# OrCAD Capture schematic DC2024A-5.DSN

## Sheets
1 PAGE5: note: HIGH CURRENT HOT SWAP CONTROLLER WITH I²C COMPATIBLE MONITORING AND EEPROM
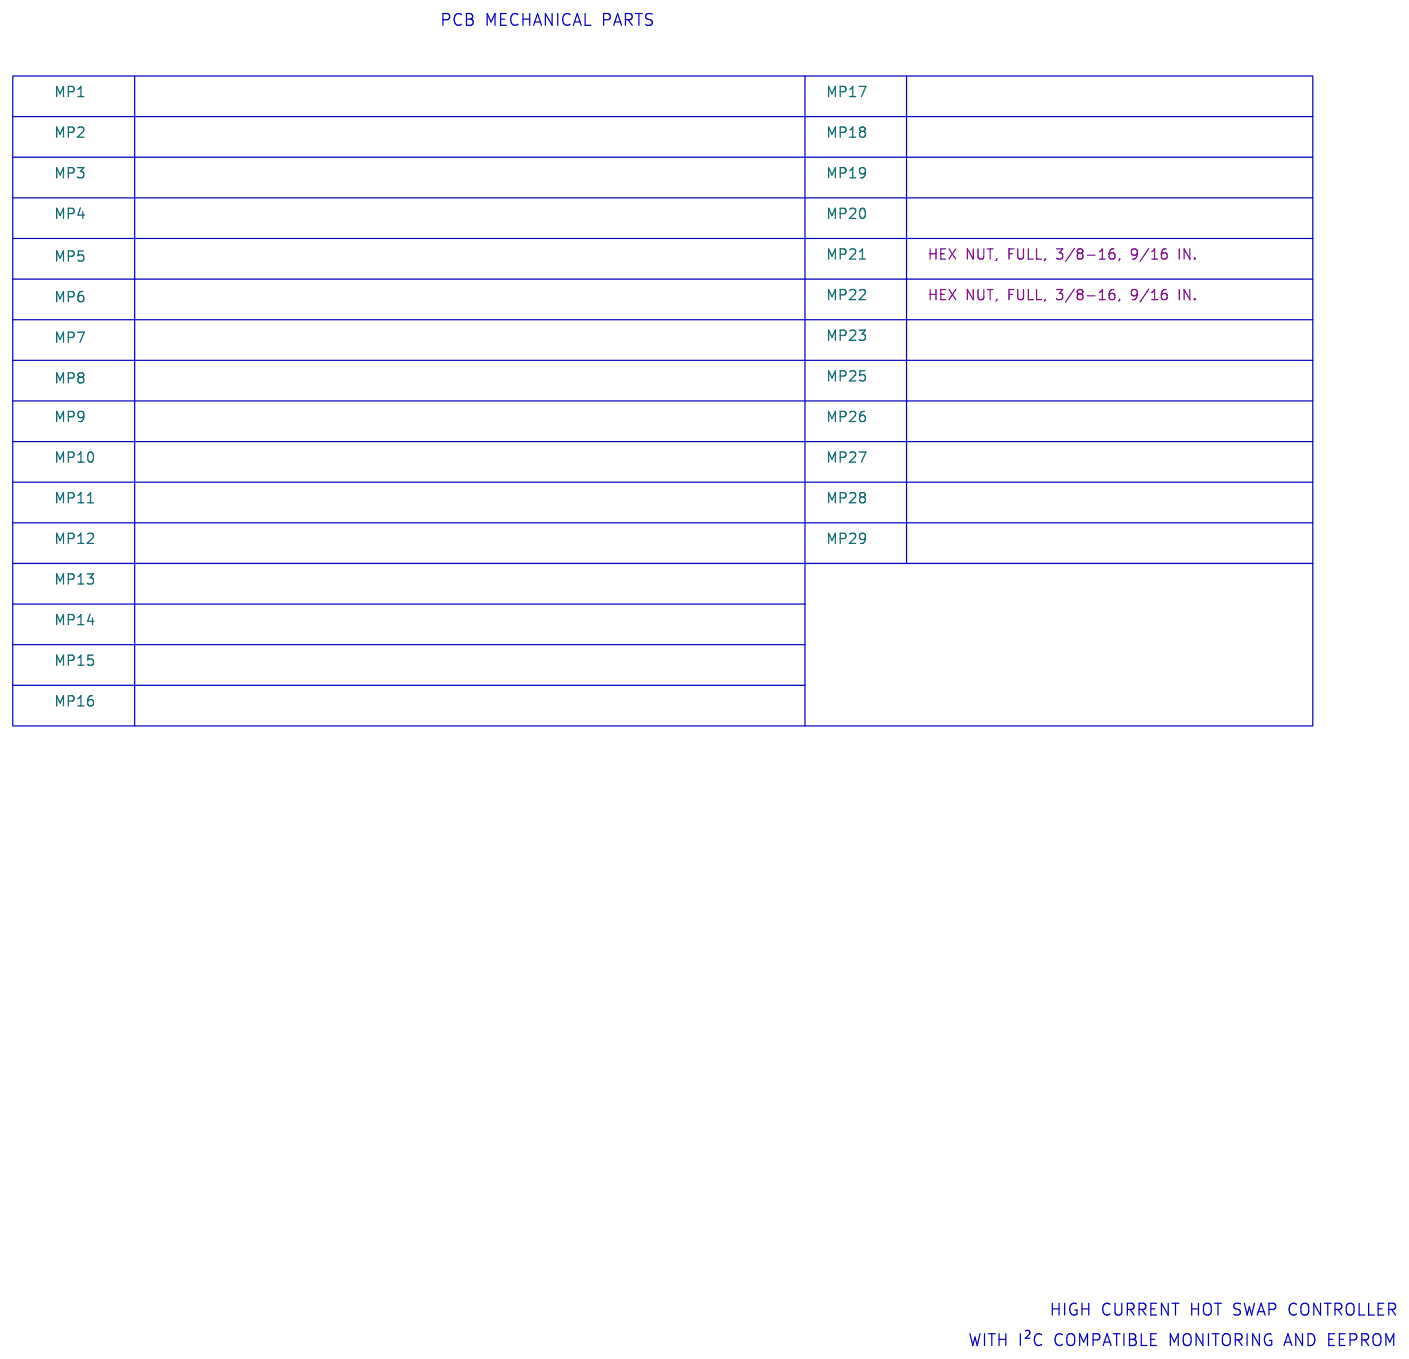
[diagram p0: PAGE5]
2 PAGE1: size Custom
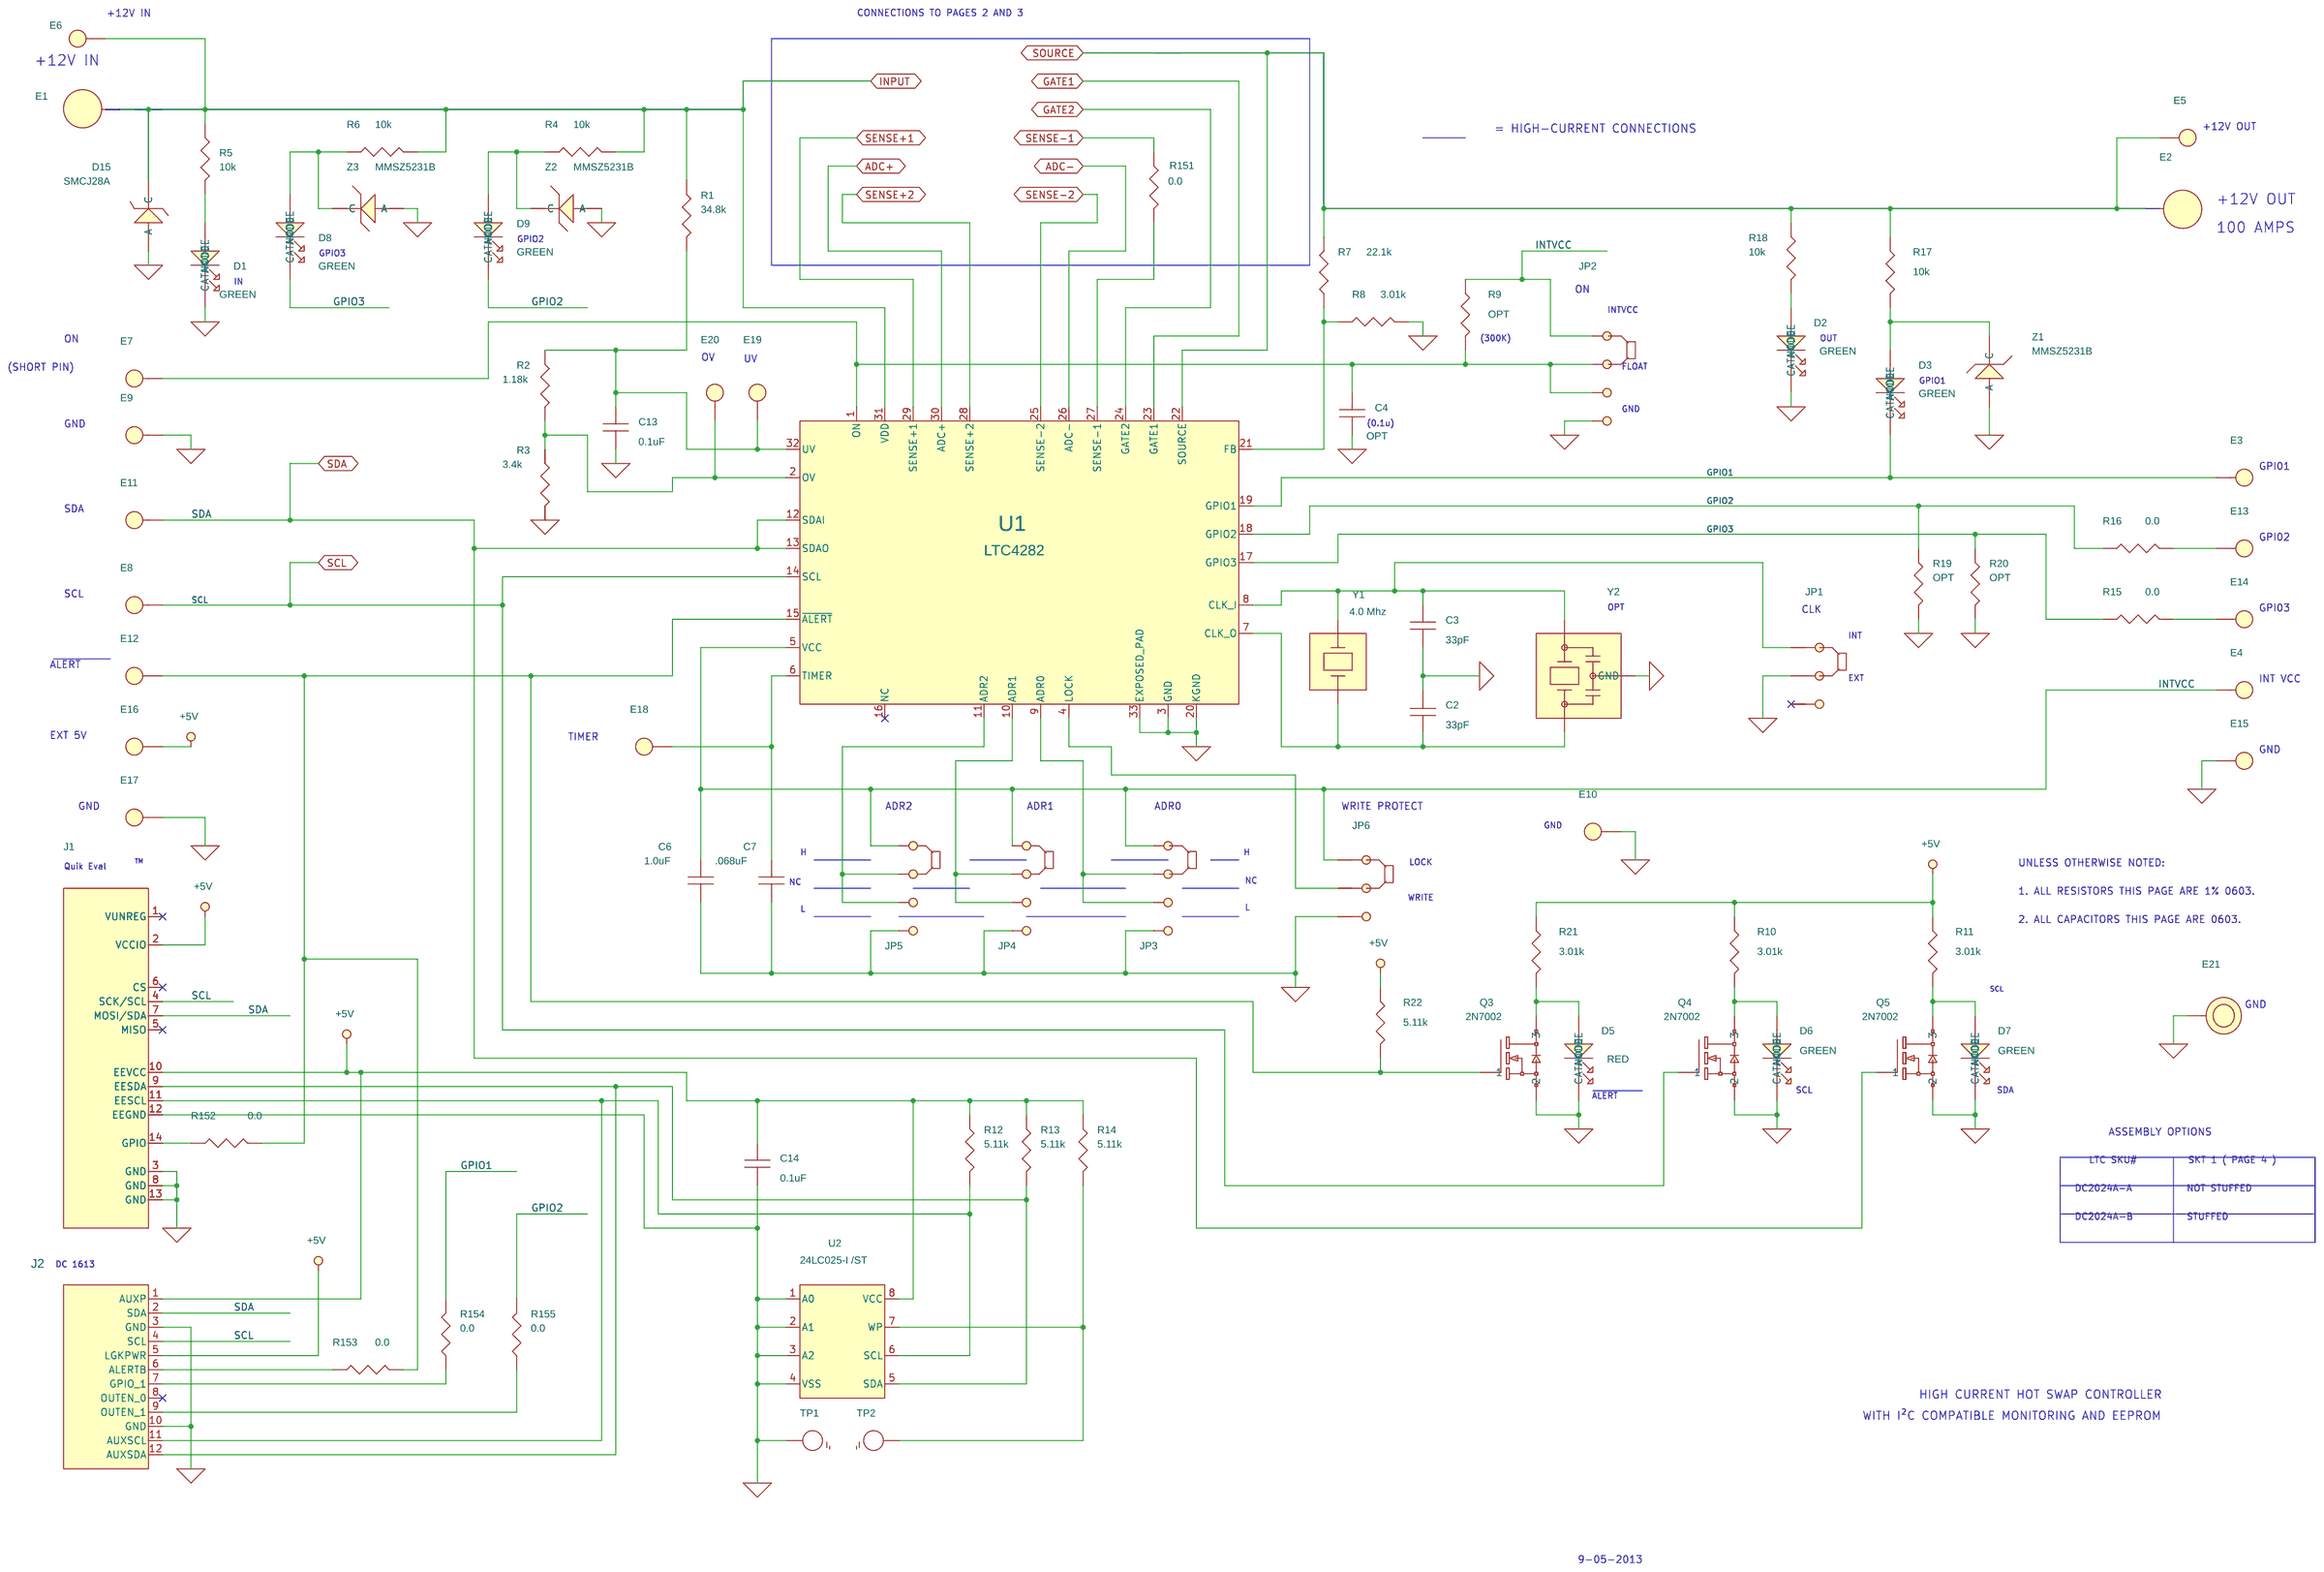
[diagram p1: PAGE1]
3 PAGE2: size Custom
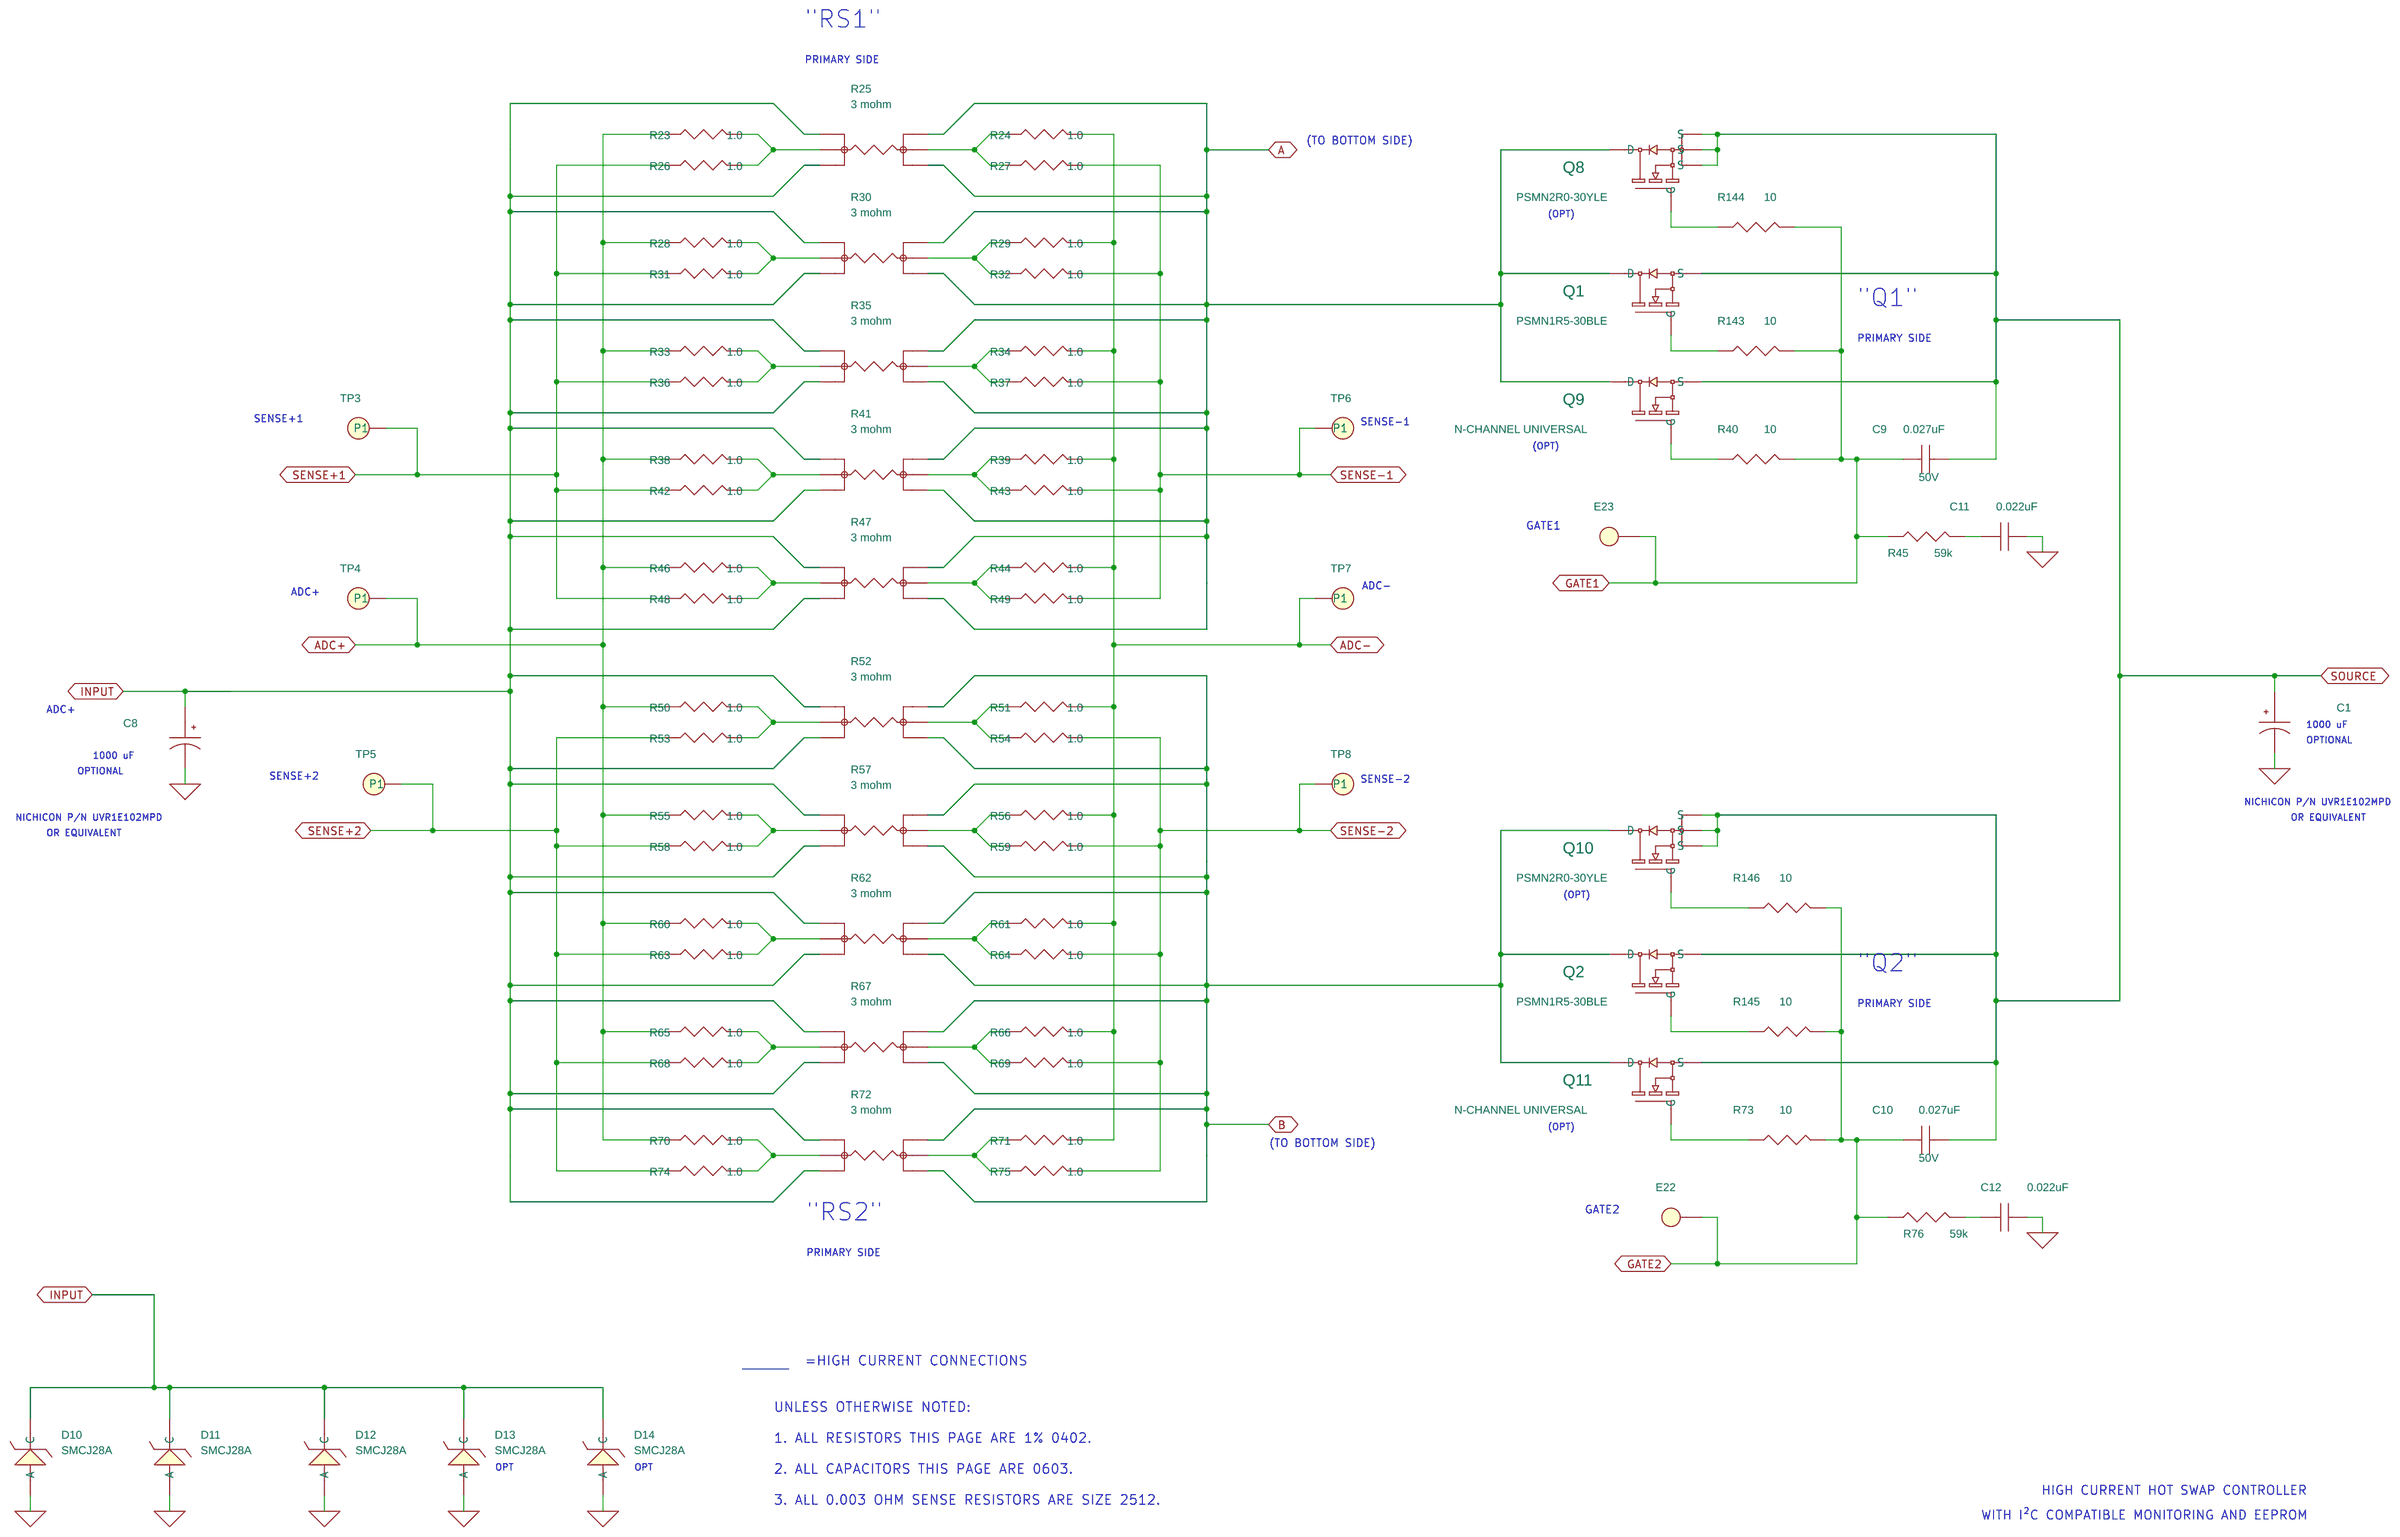
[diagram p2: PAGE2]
4 PAGE3: size Custom
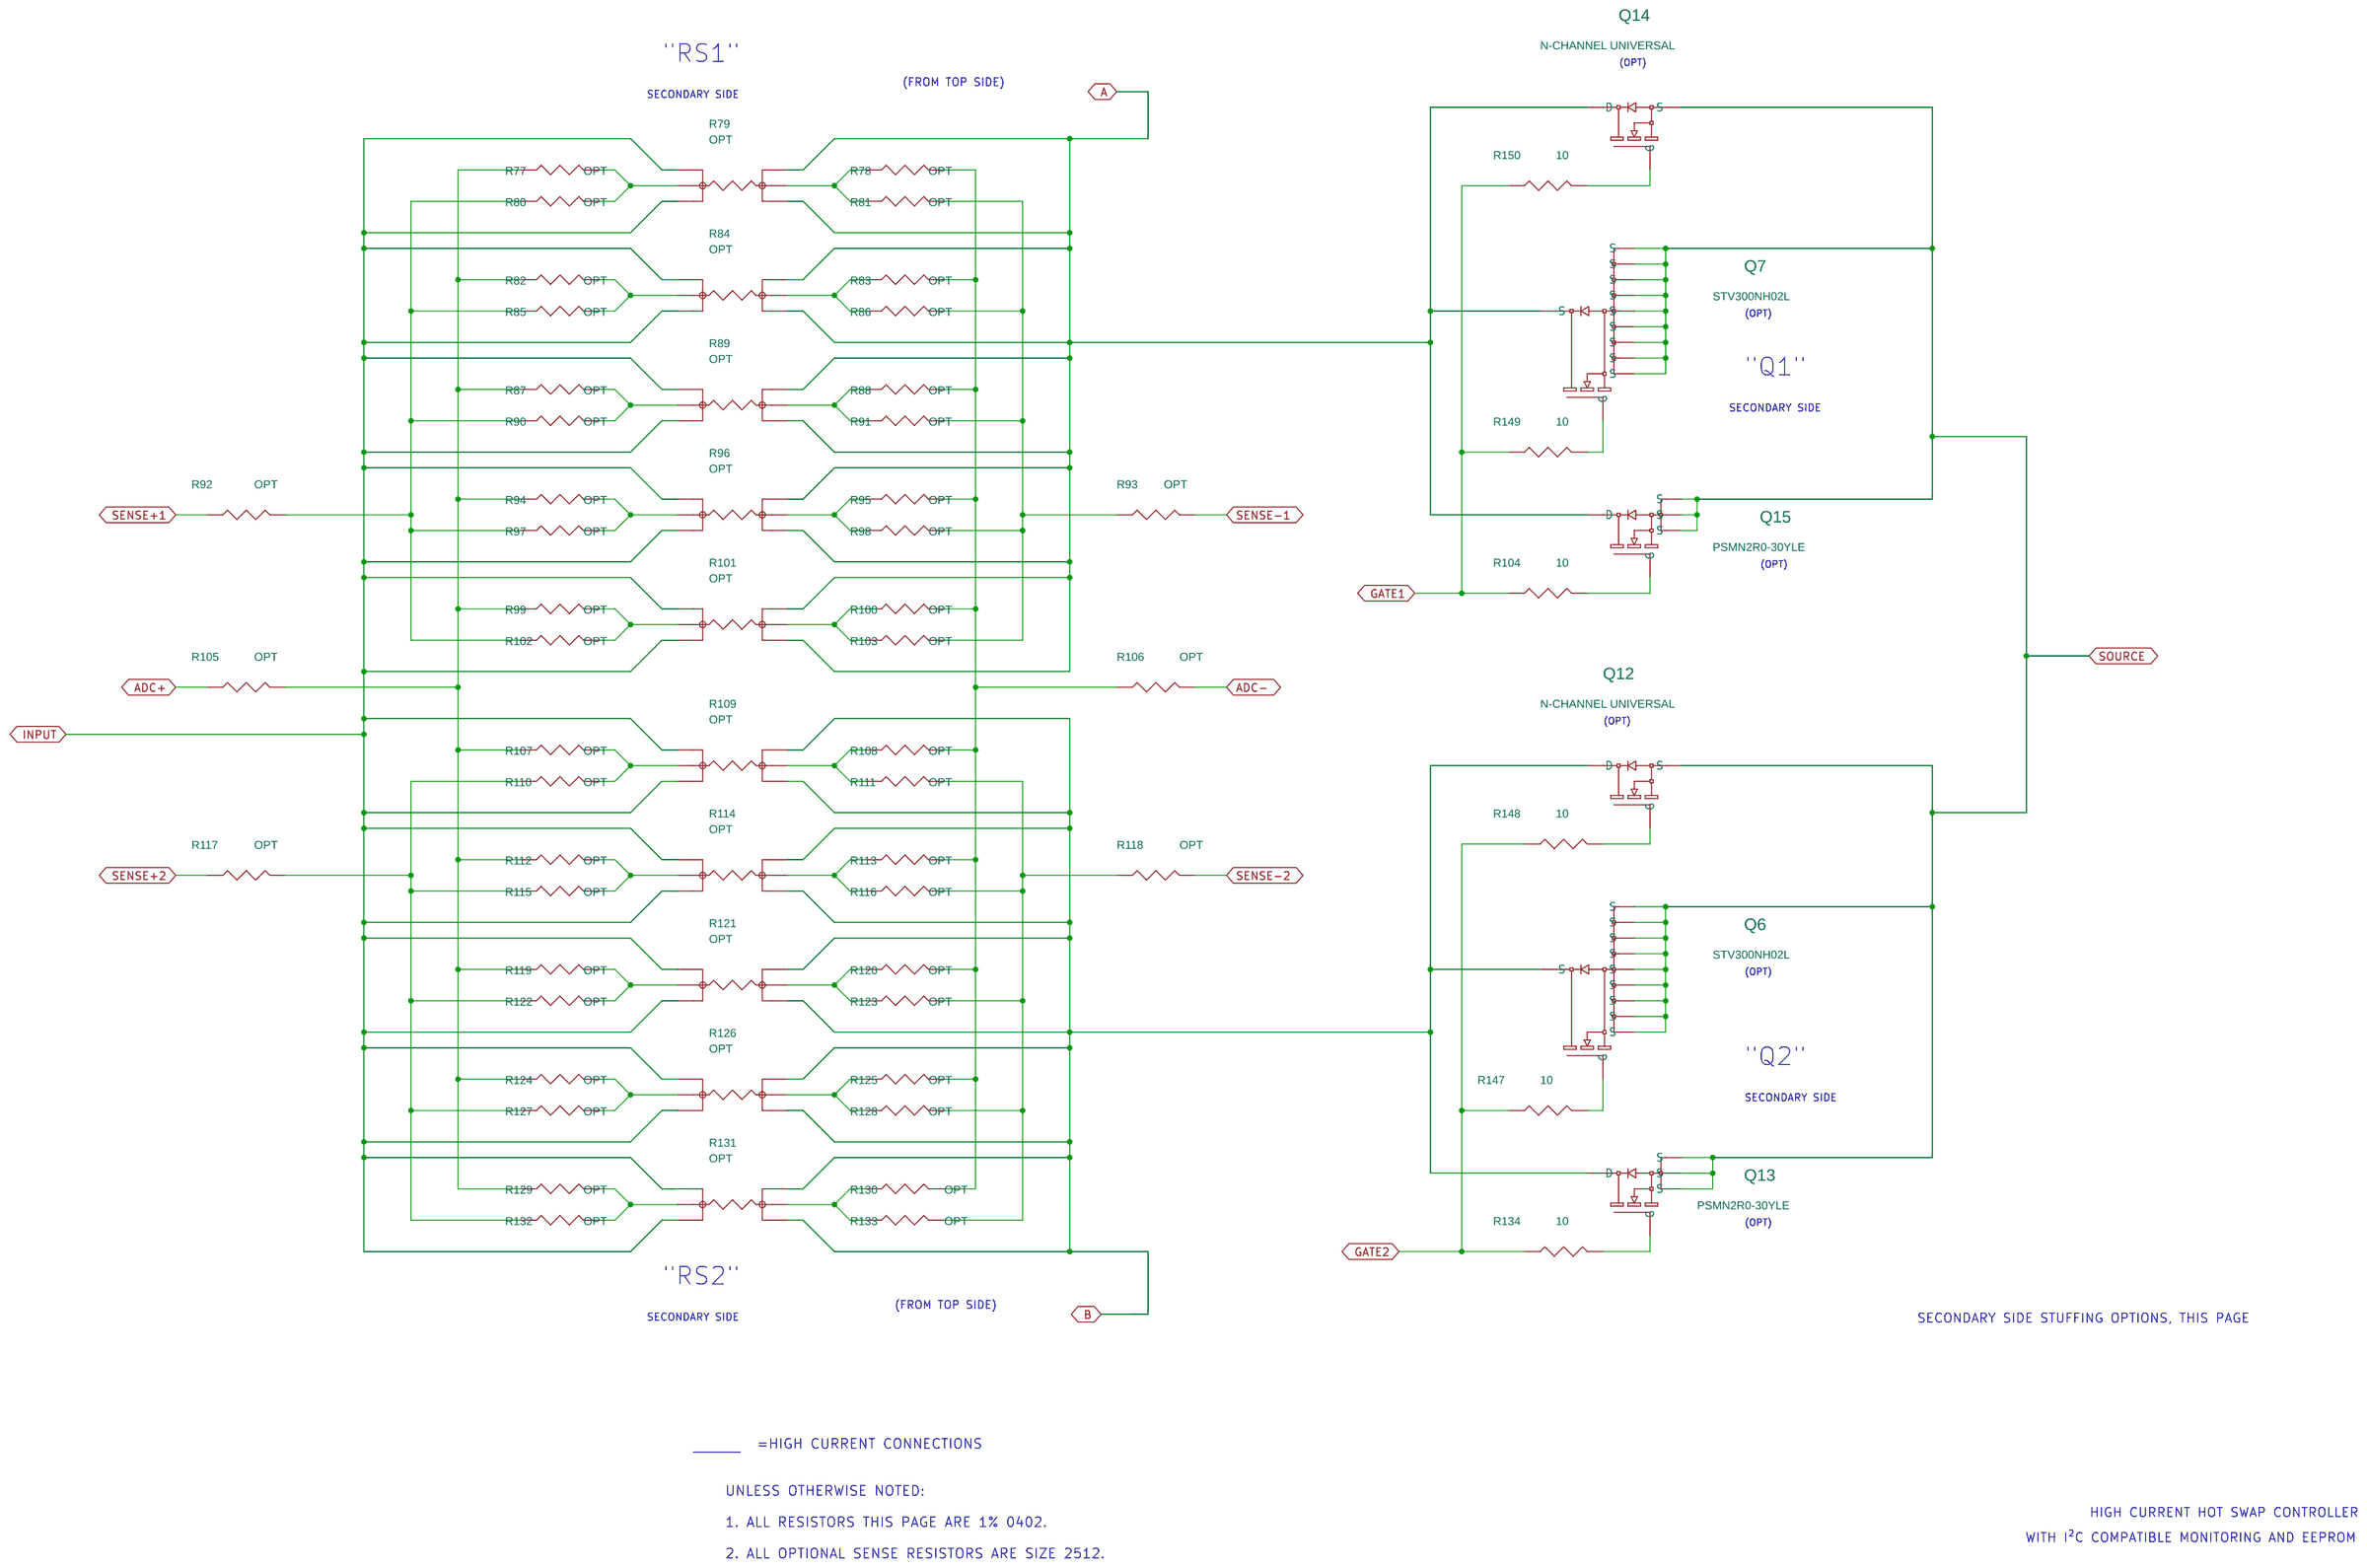
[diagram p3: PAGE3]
5 PAGE4: size Custom
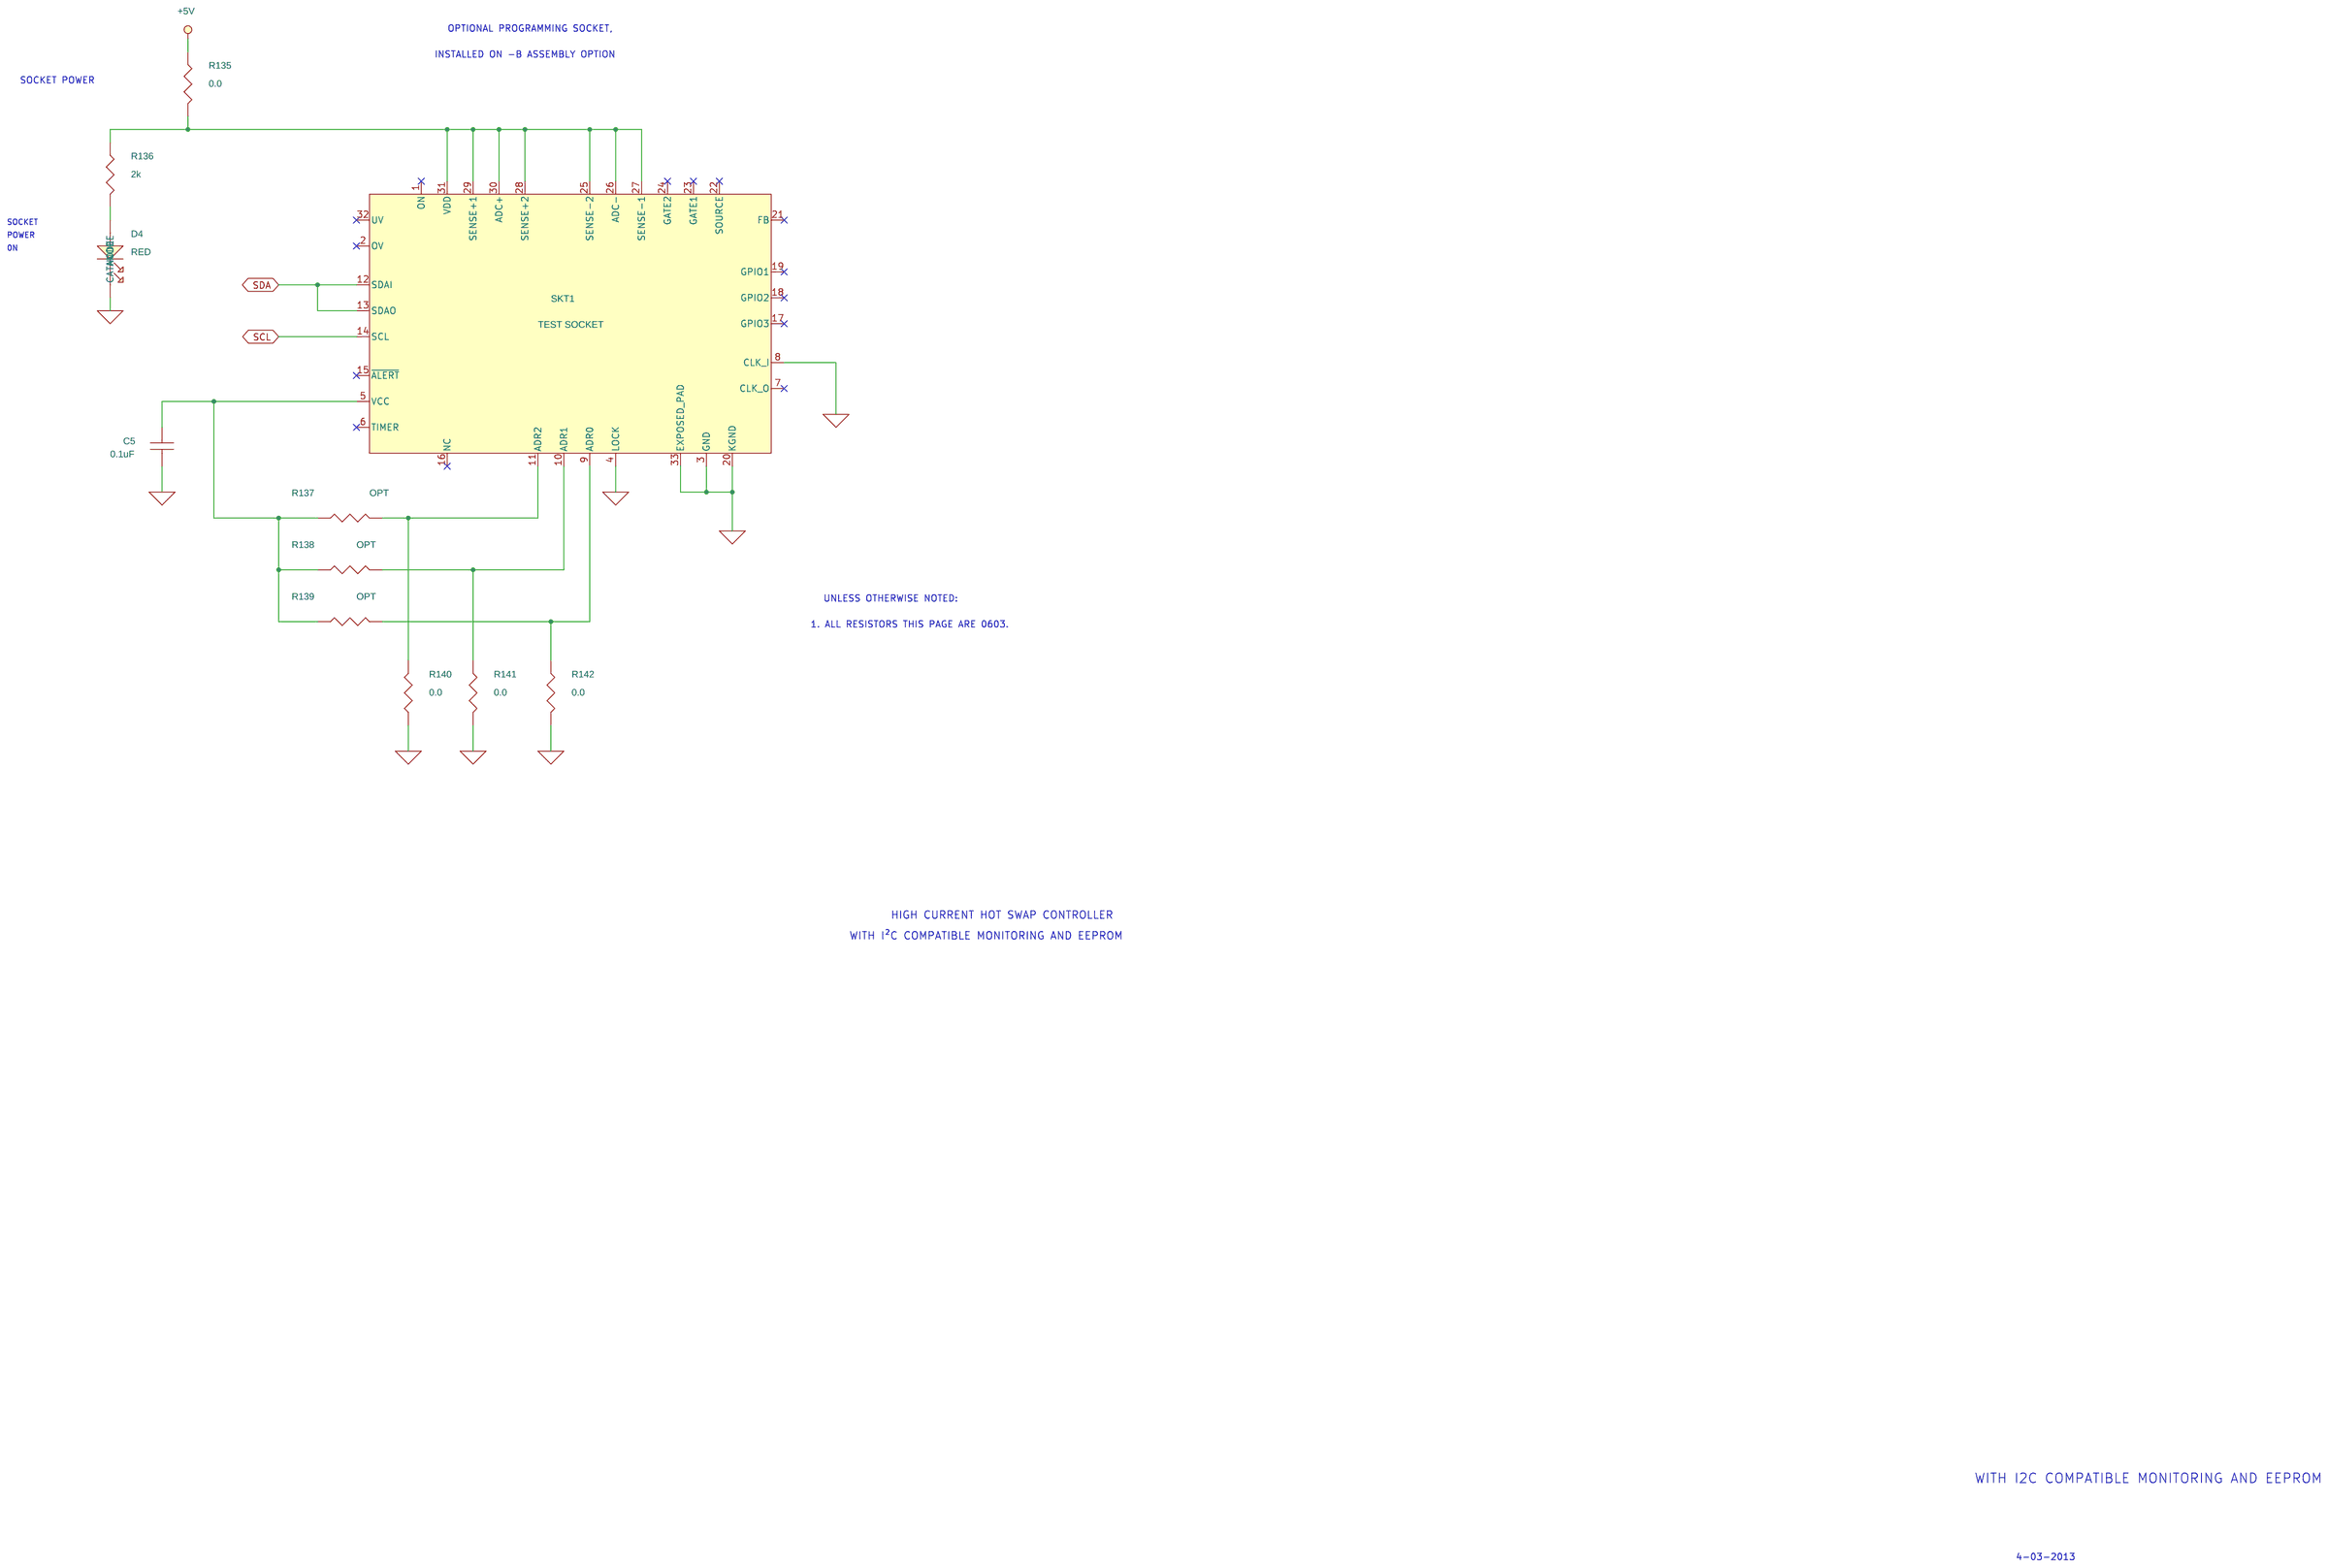
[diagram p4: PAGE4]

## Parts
sheet PAGE1
C2  33pF  [CC0603N]
C3  33pF  [CC0603N]
C4  OPT  [CC0603N]
C6  1.0uF  [CC0603N]
C7  .068uF  [CC0603N]
C13  0.1uF  [CC0603N]
C14  0.1uF  [CC0603N]
D1  GREEN  [WURTH_LED_0805]
D2  GREEN  [WURTH_LED_0805]
D3  GREEN  [WURTH_LED_0805]
D5  RED  [WURTH_LED_0805]
D6  GREEN  [WURTH_LED_0805]
D7  GREEN  [WURTH_LED_0805]
D8  GREEN  [WURTH_LED_0805]
D9  GREEN  [WURTH_LED_0805]
D15  SMCJ28A  [DIODESINC-SMC]
E1  LUG  [CB175-38-QY]
E2  LUG  [CB175-38-QY]
E3  MILL-MAX 2308  [MILLMAX2308]
E4  MILL-MAX 2308  [MILLMAX2308]
E5  MILL-MAX 2308  [MILLMAX2308]
E6  MILL-MAX 2308  [MILLMAX2308]
E7  MILL-MAX 2308  [MILLMAX2308]
E8  MILL-MAX 2308  [MILLMAX2308]
E9  MILL-MAX 2308  [MILLMAX2308]
E10  MILL-MAX 2308  [MILLMAX2308]
E11  MILL-MAX 2308  [MILLMAX2308]
E12  MILL-MAX 2308  [MILLMAX2308]
E13  MILL-MAX 2308  [MILLMAX2308]
E14  MILL-MAX 2308  [MILLMAX2308]
E15  MILL-MAX 2308  [MILLMAX2308]
E16  MILL-MAX 2308  [MILLMAX2308]
E17  MILL-MAX 2308  [MILLMAX2308]
E18  MILL-MAX 2308  [MILLMAX2308]
E19  MILL-MAX 2308  [MILLMAX2308]
E20  MILL-MAX 2308  [MILLMAX2308]
E21  BANANA_KEYSTONE-575-4  [KEY-575-4]
J1  2X7 RIBBON CONN.  [HD2X7-079-MOLEX]
J2  CONN._FCI_12 POS 2MM  [HD2X6-079-MOLEX]
JP1  3 PIN HEADER .079 SINGLE ROW B  [JP3X1/079]
JP2  4 PIN .079  [JP4X1/079]
JP3  4 PIN .079  [JP4X1/079]
JP4  4 PIN .079  [JP4X1/079]
JP5  4 PIN .079  [JP4X1/079]
JP6  3_PIN_HEADER_.079_SINGLE_ROW_B  [JP3X1/079]
PCB1  BLANK MECHANICAL PART  [MECHANICAL_PART]
Q3  2N7002  [SOT23-3N]
Q4  2N7002  [SOT23-3N]
Q5  2N7002  [SOT23-3N]
R1  34.8k  [CR0603N]
R2  1.18k  [CR0603N]
R3  3.4k  [CR0603N]
R4  10k  [CR1206N]
R5  10k  [CR1206N]
R6  10k  [CR1206N]
R7  22.1k  [CR0603N]
R8  3.01k  [CR0603N]
R9  OPT  [CR0603N]
R10  3.01k  [CR0603N]
R11  3.01k  [CR0603N]
R12  5.11k  [CR0603N]
R13  5.11k  [CR0603N]
R14  5.11k  [CR0603N]
R15  0.0  [CR0603N]
R16  0.0  [CR0603N]
R17  10k  [CR1206N]
R18  10k  [CR1206N]
R19  OPT  [CR0603N]
R20  OPT  [CR0603N]
R21  3.01k  [CR0603N]
R22  5.11k  [CR0603N]
R151  0.0  [CR0603N]
R152  0.0  [CR0603N]
R153  0.0  [CR0603N]
R154  0.0  [CR0603N]
R155  0.0  [CR0603N]
TP1  TEST PAD  [PAD70-70]
TP2  TEST PAD  [PAD70-70]
U1  LTC4282  [LTC-UH32]
U2  24LC025-I /ST  [MICROCHIP-TSSOP-8]
XJP4  2mm Ctrs.
XJP5  2mm Ctrs.
XJP6  2mm Ctrs.
XJP10  2mm Ctrs.
XJP11  2mm Ctrs.
XJP12  2mm Ctrs.
Y1  4.0 Mhz  [ABRACON-ABLS]
Y2  4 Mhz  [MURATA-CSTCR_G]
Z1  MMSZ5231B  [SOD-123N]
Z2  MMSZ5231B  [SOD-123N]
Z3  MMSZ5231B  [SOD-123N]
sheet PAGE2
C1  OPT  [CAPRD10H20LS5]
C8  OPT  [CAPRD10H20LS5]
C9  0.027uF  [CC0603N]
C10  0.027uF  [CC0603N]
C11  0.022uF  [CC0805N]
C12  0.022uF  [CC0805N]
D10  SMCJ28A  [DIODESINC-SMC]
D11  SMCJ28A  [DIODESINC-SMC]
D12  SMCJ28A  [DIODESINC-SMC]
D13  SMCJ28A  [DIODESINC-SMC]
D14  SMCJ28A  [DIODESINC-SMC]
E22  MILL-MAX 2308  [MILLMAX2308]
E23  MILL-MAX 2308  [MILLMAX2308]
Q1  PSMN1R5-30BLE  [NXP-D2PAK]
Q2  PSMN1R5-30BLE  [NXP-D2PAK]
Q8  PSMN2R0-30YLE  [SOT-669]
Q9  N-CHANNEL UNIVERSAL  [UNI-POWERFET]
Q10  PSMN2R0-30YLE  [SOT-669]
Q11  N-CHANNEL UNIVERSAL  [UNI-POWERFET]
R23  1.0  [CR0402N]
R24  1.0  [CR0402N]
R25  3 mohm  [RSENSE-2512-6PIN]
R26  1.0  [CR0402N]
R27  1.0  [CR0402N]
R28  1.0  [CR0402N]
R29  1.0  [CR0402N]
R30  3 mohm  [RSENSE-2512-6PIN]
R31  1.0  [CR0402N]
R32  1.0  [CR0402N]
R33  1.0  [CR0402N]
R34  1.0  [CR0402N]
R35  3 mohm  [RSENSE-2512-6PIN]
R36  1.0  [CR0402N]
R37  1.0  [CR0402N]
R38  1.0  [CR0402N]
R39  1.0  [CR0402N]
R40  10  [CR0603N]
R41  3 mohm  [RSENSE-2512-6PIN]
R42  1.0  [CR0402N]
R43  1.0  [CR0402N]
R44  1.0  [CR0402N]
R45  59k  [CR0603N]
R46  1.0  [CR0402N]
R47  3 mohm  [RSENSE-2512-6PIN]
R48  1.0  [CR0402N]
R49  1.0  [CR0402N]
R50  1.0  [CR0402N]
R51  1.0  [CR0402N]
R52  3 mohm  [RSENSE-2512-6PIN]
R53  1.0  [CR0402N]
R54  1.0  [CR0402N]
R55  1.0  [CR0402N]
R56  1.0  [CR0402N]
R57  3 mohm  [RSENSE-2512-6PIN]
R58  1.0  [CR0402N]
R59  1.0  [CR0402N]
R60  1.0  [CR0402N]
R61  1.0  [CR0402N]
R62  3 mohm  [RSENSE-2512-6PIN]
R63  1.0  [CR0402N]
R64  1.0  [CR0402N]
R65  1.0  [CR0402N]
R66  1.0  [CR0402N]
R67  3 mohm  [RSENSE-2512-6PIN]
R68  1.0  [CR0402N]
R69  1.0  [CR0402N]
R70  1.0  [CR0402N]
R71  1.0  [CR0402N]
R72  3 mohm  [RSENSE-2512-6PIN]
R73  10  [CR0603N]
R74  1.0  [CR0402N]
R75  1.0  [CR0402N]
R76  59k  [CR0603N]
R143  10  [CR0603N]
R144  10  [CR0603N]
R145  10  [CR0603N]
R146  10  [CR0603N]
TP3  TEST PAD  [PCBPAD-75/40]
TP4  TEST PAD  [PCBPAD-75/40]
TP5  TEST PAD  [PCBPAD-75/40]
TP6  TEST PAD  [PCBPAD-75/40]
TP7  TEST PAD  [PCBPAD-75/40]
TP8  TEST PAD  [PCBPAD-75/40]
sheet PAGE3
Q6  STV300NH02L  [STV300NH02L]
Q7  STV300NH02L  [STV300NH02L]
Q12  N-CHANNEL UNIVERSAL  [UNI-POWERFET]
Q13  PSMN2R0-30YLE  [SOT-669]
Q14  N-CHANNEL UNIVERSAL  [UNI-POWERFET]
Q15  PSMN2R0-30YLE  [SOT-669]
R77  OPT  [CR0402N]
R78  OPT  [CR0402N]
R79  OPT  [RSENSE-2512-6PIN]
R80  OPT  [CR0402N]
R81  OPT  [CR0402N]
R82  OPT  [CR0402N]
R83  OPT  [CR0402N]
R84  OPT  [RSENSE-2512-6PIN]
R85  OPT  [CR0402N]
R86  OPT  [CR0402N]
R87  OPT  [CR0402N]
R88  OPT  [CR0402N]
R89  OPT  [RSENSE-2512-6PIN]
R90  OPT  [CR0402N]
R91  OPT  [CR0402N]
R92  OPT  [CR0402N]
R93  OPT  [CR0402N]
R94  OPT  [CR0402N]
R95  OPT  [CR0402N]
R96  OPT  [RSENSE-2512-6PIN]
R97  OPT  [CR0402N]
R98  OPT  [CR0402N]
R99  OPT  [CR0402N]
R100  OPT  [CR0402N]
R101  OPT  [RSENSE-2512-6PIN]
R102  OPT  [CR0402N]
R103  OPT  [CR0402N]
R104  10  [CR0603N]
R105  OPT  [CR0402N]
R106  OPT  [CR0402N]
R107  OPT  [CR0402N]
R108  OPT  [CR0402N]
R109  OPT  [RSENSE-2512-6PIN]
R110  OPT  [CR0402N]
R111  OPT  [CR0402N]
R112  OPT  [CR0402N]
R113  OPT  [CR0402N]
R114  OPT  [RSENSE-2512-6PIN]
R115  OPT  [CR0402N]
R116  OPT  [CR0402N]
R117  OPT  [CR0402N]
R118  OPT  [CR0402N]
R119  OPT  [CR0402N]
R120  OPT  [CR0402N]
R121  OPT  [RSENSE-2512-6PIN]
R122  OPT  [CR0402N]
R123  OPT  [CR0402N]
R124  OPT  [CR0402N]
R125  OPT  [CR0402N]
R126  OPT  [RSENSE-2512-6PIN]
R127  OPT  [CR0402N]
R128  OPT  [CR0402N]
R129  OPT  [CR0402N]
R130  OPT  [CR0402N]
R131  OPT  [RSENSE-2512-6PIN]
R132  OPT  [CR0402N]
R133  OPT  [CR0402N]
R134  10  [CR0603N]
R147  10  [CR0603N]
R148  10  [CR0603N]
R149  10  [CR0603N]
R150  10  [CR0603N]
sheet PAGE4
C5  0.1uF  [CC0603N]
D4  RED  [WURTH_LED_0805]
R135  0.0  [CR0603N]
R136  2k  [CR0603N]
R137  OPT  [CR0603N]
R138  OPT  [CR0603N]
R139  OPT  [CR0603N]
R140  0.0  [CR0603N]
R141  0.0  [CR0603N]
R142  0.0  [CR0603N]
SKT1  TEST SOCKET  [32QN50S15050]
sheet PAGE5
MP1  BUMPER
MP2  BUMPER
MP3  BUMPER
MP4  BUMPER
MP5  WASHER
MP6  WASHER
MP7  WASHER
MP8  WASHER
MP9  MACHINE SCREW
MP10  MACHINE SCREW
MP11  MACHINE SCREW
MP12  MACHINE SCREW
MP13  LOCK WASHER
MP14  LOCK WASHER
MP15  LOCK WASHER
MP16  LOCK WASHER
MP17  MACHINE SCREW
MP18  MACHINE SCREW
MP19  MACHINE SCREW
MP20  MACHINE SCREW
MP21  HEX NUT
MP22  HEX NUT
MP23  WASHER
MP25  WASHER
MP26  LOCK WASHER
MP27  LOCK WASHER
MP28  HEX BOLT
MP29  HEX BOLT

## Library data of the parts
C2 C3 = CAP: CAP., 33pF, X7R, 16V, 5%, 0603; CLASS: DISCRETE; Dielectric Type: X7R; Manufacturer: AVX; Manufacturer PN: 0603YC330JAT2A; PART_NUMBER: TMP-28; Package Size: 0603; Rated Voltage: 16V; Tolerance: 5%
C4 = CAP: CAP., OPTION, 0603; CLASS: DISCRETE; Manufacturer: N/A; Manufacturer PN: N/A; PART_NUMBER: 150-3038; Package Size: 0603
C6 = CAP: CAP., 1uF, X7R, 16V, 10%, 0603; CLASS: DISCRETE; Dielectric Type: X7R; Manufacturer: AVX; Manufacturer PN: 0603YC105KAT2A; PART_NUMBER: 150-3384; Package Size: 0603; Rated Voltage: 16V; Tolerance: 10%
C7 = CAP: CAP., 0.068uF X7R, 16V, 10%, 0603; CLASS: DISCRETE; FPLIST: CC0603N,CC0603L,CC0603M; Manufacturer: AVX; Manufacturer PN: 0603YC683KAT2A; PART_NUMBER: TMP-985; Package Size: 0603; Rated Voltage: 16VDC; Temperature Coefficient: X7R; Tolerance: 10%
C13 = CAP: CAP., 0.1uF, X7R, 25V, 20%, 0603; CLASS: DISCRETE; Dielectric Type: X7R; Manufacturer: TDK; Manufacturer PN: C1608X7R1E104M080AA; PART_NUMBER: 150-3402; Package Size: 0603; Rated Voltage: 25V; Tolerance: 20%
C5 C14 = CAP: CAP., 0.1uF, X7R, 16V,10%, 0603; CLASS: DISCRETE; Dielectric Type: X7R; Manufacturer: AVX; Manufacturer PN: 0603YC104KAT2A; PART_NUMBER: 150-0164; Package Size: 0603; Rated Voltage: 16V; Tolerance: 10%
D1-D3 D6-D9 = LED_GREEN_0805_WURTH: CLASS: DISCRETE; Manufacturer PN: 150080GS75000; PART_NUMBER: 270-0063; Package Size: 0805
D4 D5 = LED_RED_0805_WURTH: CLASS: DISCRETE; Manufacturer PN: 150080RS75000; PART_NUMBER: TMP-622; Package Size: 0805
D10-D15 = DIODE_TVS_SMCJ28A_SMC: CLASS: DISCRETE; Manufacturer PN: SMCJ28A-13; PART_NUMBER: TMP-648; Package Size: SMC; Rated Voltage: 24V
E1 E2 = TONGUE_LUG_3_8_STUD: CLASS: MECHANICAL PART; PART_NUMBER: TMP-873
E3-E20 E22 E23 = TEST_POINT_2308_.125_THK_BD: TEST POINT, TURRET, .064 MTG. HOLE, .125" THICK PCB"; CLASS: IO; Manufacturer PN: 2308-4-00-80-00-00-07-0; PART_NUMBER: TMP-858
E21 = BANANA_KEYSTONE-575-4: CLASS: IO; Manufacturer PN: 575-4; PART_NUMBER: 250-0428
J1 = CONN_2X7_.079_MOLEX_RIBBON_A: CONN.,HEADER,SHROUDED,2X7,2mm,THT; CLASS: IO; Manufacturer PN: 87831-1420; PART_NUMBER: 250-0403
J2 = CONN._FCI_12_POS_2MM: CLASS: IO; Manufacturer PN: 98414-G06-12ULF; PART_NUMBER: TMP-673
JP1 JP6 = 3_PIN_HEADER_.079_SINGLE_ROW_B: CLASS: IO; Manufacturer PN: TMM-103-02-L-S; PART_NUMBER: 250-0422
JP2-JP5 = 4_PIN_HEADER_.079_SINGLE_ROW_C: CONN., HEADER, 1x4, 2mm, THRU-HOLE, VERTICAL; CLASS: IO; Manufacturer: SAMTEC; Manufacturer PN: TMM-104-02-L-S; PART_NUMBER: TMP-692
PCB1 = BLANK_MECHANICAL_PART: FAB, DC2024A; CLASS: MECHANICAL PART; Manufacturer: BAY AREA CIRCUITS; Manufacturer PN: 600-DC2024AA REV.01; PART_NUMBER: 600-DC2024AA REV.01
Q3-Q5 = 2N7002_SOT-23: TRANS.,MOSFET N-CH., 60V SOT-23; CLASS: DISCRETE; Manufacturer PN: 2N7002K-T1-GE3; PART_NUMBER: TMP-577; Package Size: SOT-23
R1 = RES: RES., 34.8k, 1/10W, 1%, 0603; CLASS: DISCRETE; Manufacturer: YAGEO; Manufacturer PN: RC0603FR-0734K8L; PART_NUMBER: TMP-446; Package Size: 0603; Rated Power: 1/10W; Tolerance: 1%
R2 = RES: RES., 1.18k, 1/10W, 1%, 0603; CLASS: DISCRETE; Manufacturer: YAGEO; Manufacturer PN: RC0603FR-071K18L; PART_NUMBER: TMP-428; Package Size: 0603; Rated Power: 1/10W; Tolerance: 1%
R3 = RES: RES., 3.4k, 1/10W, 1%, 0603; CLASS: DISCRETE; Manufacturer: YAGEO; Manufacturer PN: RC0603FR-073K4L; PART_NUMBER: TMP-448; Package Size: 0603; Rated Power: 1/10W; Tolerance: 1%
R4-R6 R17 R18 = RES: RES., 10k, 1/4W, 5%, 1206; CLASS: DISCRETE; Manufacturer: PANASONIC; Manufacturer PN: ERJ-8GEYJ103V; PART_NUMBER: 100-0317; Package Size: 1206; Rated Power: 1/4W; Tolerance: 5%
R7 = RES: RES., 22.1k, 1/10W, 1%, 0603; CLASS: DISCRETE; Manufacturer: YAGEO; Manufacturer PN: RC0603FR-0722K1L; PART_NUMBER: TMP-437; Package Size: 0603; Rated Power: 1/10W; Tolerance: 1%
R8 R10 R11 R21 = RES: RES., 3.01k, 1/10W, 1%, 0603; CLASS: DISCRETE; Manufacturer: YAGEO; Manufacturer PN: RC0603FR-073K01L; PART_NUMBER: TMP-447; Package Size: 0603; Rated Power: 1/10W; Tolerance: 1%
R9 R19 R20 R137-R139 = RES: RES., OPTION, 0603; CLASS: DISCRETE; Manufacturer: N/A; Manufacturer PN: N/A; PART_NUMBER: 100-2374; Package Size: 0603; Rated Power: N/A; Tolerance: N/A
R12-R14 R22 = RES: RES., 5.11k, 1/10W, 1%, 0603; CLASS: DISCRETE; Manufacturer: YAGEO; Manufacturer PN: RC0603FR-075K11L; PART_NUMBER: 100-2603; Package Size: 0603; Rated Power: 1/10W; Tolerance: 1%
R15 R16 R135 R140-R142 R151-R155 = RES: RES., 0 OHMS, 1/10W, 0603; CLASS: DISCRETE; Manufacturer: Yageo; Manufacturer PN: RC0603JR-070RL; PART_NUMBER: 100-0009; Package Size: 0603; Rated Power: 1/10W; Tolerance: Jumper
TP1 TP2 = TESTPOINT_SMT_60_MIL: TESTPOINT, PCB COPPER FEATURE; CLASS: IO; FPLIST: TP-SMT/60,PAD-30MIL_HI-FREQTESTPOINT,TP-TESTJIG,TP-SMT/60, PCBPAD-75/40,PAD70-70; Manufacturer: N/A; Manufacturer PN: N/A; PART_NUMBER: TMP-667
U1 = LTC4282: CLASS: IC; Manufacturer: LINEAR TECH.; Manufacturer PN: LTC4282CUH#PBF; PART_NUMBER: TMP-796; Package Size: UH-32; Part Number: LINEAR TECH., LTC4282CUH#PBF
U2 = 24LC025-I_ST_TSSOP-8: IC, MEMORY,EEPROM Serial-I2C,2K-bit,TSSOP-8; CLASS: IC; Manufacturer: Microchip; Manufacturer PN: 24LC025-I/ST; PART_NUMBER: 380-0087; Package Size: TSSOP-8
XJP4-XJP6 XJP10-XJP12 = SHUNT_2MM: CONN.,SHUNT,2PIN,2mm; CLASS: IO; Manufacturer PN: 2SN-BK-G; PART_NUMBER: 250-0419
Y1 = XTAL_4MHZ_ABLS: CLASS: DISCRETE; Manufacturer: ABRACON; Manufacturer PN: ABLS-4.000MHZ-B4-T; PART_NUMBER: TMP-832
Y2 = 4_MHZ_RESONATOR: CLASS: DISCRETE; Manufacturer: MURATA; Manufacturer PN: CSTCR4M00G53-R0; PART_NUMBER: TMP-851
Z1-Z3 = ZENER_5.1V_MMSZ5231B_SOD123: CLASS: DISCRETE; Manufacturer: FAIRCHILD; PART_NUMBER: TMP-658; Package Size: SOD-123; Rated Voltage: 5.1V
C1 C8 = CAP_P: CAP., POLARIZED, OPTION; CLASS: DISCRETE; Manufacturer: N/A; Manufacturer PN: N/A; PART_NUMBER: TMP-214
C9 C10 = CAP: CAP CER 0.027UF 50V 10% X7R 0603; CLASS: DISCRETE; Dielectric Type: Capacitors; Manufacturer: AVX Corporation; Manufacturer PN: 06035C273KAT2A; PART_NUMBER: TMP-916; Package Size: 0603; Rated Voltage: 50V; Temperature Coefficient: X7R; Tolerance: 10%
C11 C12 = CAP: CAP., 0.022uF, X7R, 50V, 5%, 0805; CLASS: DISCRETE; Dielectric Type: Capacitors; FPLIST: CC0805N,CC0805L,CC0805M; Manufacturer: Kemet; Manufacturer PN: C0805C223J5RACTU; PART_NUMBER: TMP-987; Package Size: 0805 (2012 Metric); Rated Voltage: 50V; Temperature Coefficient: X7R; Tolerance: 5%
Q1 = PSMN1R5-30BLE: TRANSISTOR, MOSFET, D2PAK; CLASS: DISCRETE; Manufacturer: NXP; Manufacturer PN: PSMN1R5-30BLE,118; PART_NUMBER: TMP-573; Package Size: D2PAK
Q2 = PSMN1R5-30BLE: CLASS: DISCRETE; Manufacturer: NXP; Manufacturer PN: PSMN1R5-30BLE,118; PART_NUMBER: TMP-573; Package Size: D2PAK
Q8 Q10 Q13 Q15 = PSMN2R0-30YLE: TRANSISTOR, MOSFET, N-CH., SOT-669; CLASS: DISCRETE; Manufacturer: NXP; PART_NUMBER: TMP-580; Package Size: SOT669
Q9 Q11 Q12 Q14 = N-CH_UNIVERSAL: OPTION; CLASS: DISCRETE; Manufacturer: N/A; Manufacturer PN: N/A; PART_NUMBER: TMP-605
R23 R24 R26-R29 R31-R34 R36-R39 R42-R44 R46 R48-R51 R53-R56 R58-R61 R63-R66 R68-R71 R74 R75 = RES: RES., 1 OHM, 1/16W, 1%, 0402; CLASS: DISCRETE; Manufacturer: VISHAY; Manufacturer PN: CRCW04021R00FKED; PART_NUMBER: TMP-252; Package Size: 0402; Rated Power: 1/16W; Tolerance: 1%
R25 R30 R35 R41 R47 R52 R57 R62 R67 R72 = 0.001_OHMS_1%_1W_2512_6PIN: RES., 0.003 OHMS, METAL ELEMENT, 1%,  2W 2512; CLASS: DISCRETE; Manufacturer: Optek Technology (TT electronics); Manufacturer PN: LRMAT2512-R003FT4; PART_NUMBER: TMP-915; Package Size: 2512; Rated Power: 2 W; Temperature Coefficient: 100
R40 R73 R104 R134 R143-R150 = RES: RES., 10 OHMS, 1/10W, 5%, 0603; CLASS: DISCRETE; Manufacturer: YAGEO; Manufacturer PN: RC0603JR-0710RL; PART_NUMBER: TMP-464; Package Size: 0603; Rated Power: 1/10W; Tolerance: 5%
R45 R76 = RES: RES., 59k, 1/10W, 1%, 0603; CLASS: DISCRETE; FPLIST: CR0603N,CR0603L,CR0603M; Manufacturer: Vishay Dale; Manufacturer PN: CRCW060359K0FKEA; PART_NUMBER: TMP-988; Package Size: 0603 (1608 Metric); Rated Power: 0.1W, 1/10W; Temperature Coefficient: 100ppm/C; Tolerance: 1%
TP3-TP8 = TEST_PAD_COPPER_FEATURE: TESTPOINT, PCB COPPER FEATURE; CLASS: IO; FPLIST: TP-SMT/60,PAD-30MIL_HI-FREQTESTPOINT,TP-TESTJIG,TP-SMT/60,PCBPAD-75/40,PAD70-70; Manufacturer: N/A; Manufacturer PN: N/A; PART_NUMBER: TMP-667
Q6 Q7 = STV300NH02L: TRANSISTOR, MOSFET,N-CH., SO-10; CLASS: DISCRETE; Manufacturer: ST MICROELECTRONICS; PART_NUMBER: TMP-596; Part Number: OPTION
R77 R78 R80-R83 R85-R88 R90-R95 R97-R100 R102 R103 R105-R108 R110-R113 R115-R120 R122-R125 R127-R130 R132 R133 = RES: RES., OPTION, 0402; CLASS: DISCRETE; Manufacturer: N/A; Manufacturer PN: N/A; PART_NUMBER: 100-0357; Package Size: 0402; Rated Power: N/A; Tolerance: N/A
R79 R84 R89 R96 R101 R109 R114 R121 R126 R131 = 0.001_OHMS_1%_1W_2512_6PIN: RES., OPTION, 2512; CLASS: DISCRETE; PART_NUMBER: TMP-921; Package Size: 2512; Rated Power: 2W
R136 = RES: RES.,2k,OHMS,1%,1/10W,0603; CLASS: DISCRETE; Manufacturer: NIC; Manufacturer PN: NRC06F2001TRF; PART_NUMBER: 100-2313; Package Size: 0603; Rated Power: 1/10W; Tolerance: 1%
SKT1 = LTC4282: CLAMSHELL TEST SOCKET, QFN 32; CLASS: IC; Manufacturer: PLASTRONICS; PART_NUMBER: TMP-920; Package Size: UH-32; Part Number: PLASTRONICS, 32QN50S15050
MP1-MP4 = BUMPER_#4_RECESSED_BLK: CLASS: MECHANICAL PART; Manufacturer PN: 727; PART_NUMBER: TMP-875
MP5-MP8 = FLAT_WASHER_SS_18-8_#4: CLASS: MECHANICAL PART; Manufacturer PN: 5563; PART_NUMBER: TMP-861
MP9-MP12 = #4-40_X_1_2_PH._PAN_HD._SCREW: CLASS: MECHANICAL PART; Manufacturer PN: 7593; PART_NUMBER: TMP-879
MP13-MP16 = LOCK_WASHER_#4_INT_ZINC: CLASS: MECHANICAL PART; Manufacturer PN: 3011; PART_NUMBER: TMP-870
MP17-MP20 = #4-40_HEX_NUT_SS_18-8: CLASS: MECHANICAL PART; Manufacturer PN: 4115; PART_NUMBER: TMP-871
MP21 MP22 = HEX_NUT_3_8-16_9_16_IN: HEX NUT, FULL, 3/8-16, 9/16 IN.; CLASS: MECHANICAL PART; Manufacturer PN: 1WB27; PART_NUMBER: TMP-909
MP23 MP25 = FLAT_WASHER_SS_18-8_3_8_IN: CLASS: MECHANICAL PART; Manufacturer PN: 6FDG6; PART_NUMBER: TMP-910
MP26 MP27 = LOCK_WASHER_INT_0.398_IN_ID: CLASS: MECHANICAL PART; Manufacturer PN: 2DE18; PART_NUMBER: TMP-911
MP28 MP29 = HEX_HEAD_BOLT_3_8_16_X_1_1_8: CLASS: MECHANICAL PART; Manufacturer PN: 30Z861; PART_NUMBER: TMP-912

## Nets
+5V: C14.1 E16.1(A) J1.2(VCCIO) J1.10(EEVCC) J2.1(AUXP) J2.5(LGKPWR) R10.1 R11.1 R12.1 R13.1 R14.1 R21.1 R22.1 R135.1 U2.8(VCC)
GND_SIGNAL: C1.2 C2.2 C3.2 C4.2 C5.2 C6.2 C7.2 C8.2 C11.1 C12.1 C13.2 C14.2 D1.1(CATHODE) D2.1(CATHODE) D4.1(CATHODE) D5.1(CATHODE) D6.1(CATHODE) D7.1(CATHODE) D10.2(A) D11.2(A) D12.2(A) D13.2(A) D14.2(A) D15.2(A) E9.1(A) E10.1(A) E15.1(A) E17.1(A) E21.1 J1.3(GND) J1.8(GND) J1.12(EEGND) J1.13(GND) J2.3(GND) J2.10(GND) JP1.2 JP2.4 JP3.4 JP4.4 JP5.4 JP6.3 Q3.2 Q4.2 Q5.2 R3.2 R8.2 R19.2 R20.2 R140.2 R141.2 R142.2 SKT1.3(GND) SKT1.4(LOCK) SKT1.8(CLK_I) SKT1.20(KGND) SKT1.33(EXPOSED_PAD) TP1.1 U1.3(GND) U1.20(KGND) U1.33(EXPOSED_PAD) U2.1(A0) U2.2(A1) U2.3(A2) U2.4(VSS) Y2.2(GND) Z1.2(A) Z2.2(A) Z3.2(A)
A: Q1.4(D) Q7.11(S) Q8.5(D) Q9.3(D) Q14.3(D) Q15.5(D) R25.4 R25.6 R30.4 R30.6 R35.4 R35.6 R41.4 R41.6 R47.4 R47.6 R79.4 R79.6 R84.4 R84.6 R89.4 R89.6 R96.4 R96.6 R101.4 R101.6
ADC+: R23.1 R28.1 R33.1 R38.1 R46.1 R50.1 R55.1 R60.1 R65.1 R70.1 R105.1 TP4.1(P1) U1.30(ADC+)
ADC-: R24.2 R29.2 R34.2 R39.2 R44.2 R51.2 R56.2 R61.2 R66.2 R71.2 R106.2 TP7.1(P1) U1.26(ADC-)
B: Q2.4(D) Q6.11(S) Q10.5(D) Q11.3(D) Q12.3(D) Q13.5(D) R52.4 R52.6 R57.4 R57.6 R62.4 R62.6 R67.4 R67.6 R72.4 R72.6 R109.4 R109.6 R114.4 R114.6 R121.4 R121.6 R126.4 R126.6 R131.4 R131.6
GATE1: C9.1 E23.1(A) R40.2 R45.2 R104.1 R143.2 R144.2 R149.1 R150.1 U1.23(GATE1)
GATE2: C10.1 E22.1(A) R73.2 R76.2 R134.1 R145.2 R146.2 R147.1 R148.1 U1.24(GATE2)
GPIO1: D3.1(CATHODE) E3.1(A) R154.2 U1.19(GPIO1)
GPIO2: D9.1(CATHODE) R16.1 R19.1 R155.2 U1.18(GPIO2)
GPIO3: D8.1(CATHODE) R15.1 R20.1 U1.17(GPIO3)
INPUT: C8.1 D10.1(C) D11.1(C) D12.1(C) D13.1(C) D14.1(C) D15.1(C) E1.1 E6.1(A) R1.1 R4.2 R5.1 R6.1 R25.3 R25.5 R30.3 R30.5 R35.3 R35.5 R41.3 R41.5 R47.3 R47.5 R52.3 R52.5 R57.3 R57.5 R62.3 R62.5 R67.3 R67.5 R72.3 R72.5 R79.3 R79.5 R84.3 R84.5 R89.3 R89.5 R96.3 R96.5 R101.3 R101.5 R109.3 R109.5 R114.3 R114.5 R121.3 R121.5 R126.3 R126.5 R131.3 R131.5 U1.31(VDD)
INTVCC: C6.1 E4.1(A) JP2.1 JP3.1 JP4.1 JP5.1 JP6.1 R9.1 U1.5(VCC)
SCL: E8.1(A) J1.4(SCK/SCL) J2.4(SCL) Q4.1 SKT1.14(SCL) U1.14(SCL)
SDA: E11.1(A) J1.7(MOSI/SDA) J2.2(SDA) Q5.1 SKT1.12(SDAI) SKT1.13(SDAO) U1.12(SDAI) U1.13(SDAO)
SENSE+1: R26.1 R31.1 R36.1 R42.1 R48.1 R92.1 TP3.1(P1) U1.29(SENSE+1)
SENSE+2: R53.1 R58.1 R63.1 R68.1 R74.1 R117.1 TP5.1(P1) U1.28(SENSE+2)
SENSE-1: R27.2 R32.2 R37.2 R43.2 R49.2 R93.2 R151.1 TP6.1(P1)
SENSE-2: R54.2 R59.2 R64.2 R69.2 R75.2 R118.2 TP8.1(P1) U1.25(SENSE-2)
SOURCE: C1.1 C9.2 C10.2 E2.1 E5.1(A) Q1.3(S) Q2.3(S) Q6.2(S) Q6.3(S) Q6.4(S) Q6.5(S) Q6.6(S) Q6.7(S) Q6.8(S) Q6.9(S) Q6.10(S) Q7.2(S) Q7.3(S) Q7.4(S) Q7.5(S) Q7.6(S) Q7.7(S) Q7.8(S) Q7.9(S) Q7.10(S) Q8.1(S) Q8.2(S) Q8.3(S) Q9.2(S) Q10.1(S) Q10.2(S) Q10.3(S) Q11.2(S) Q12.2(S) Q13.1(S) Q13.2(S) Q13.3(S) Q14.2(S) Q15.1(S) Q15.2(S) Q15.3(S) R7.2 R17.1 R18.1 U1.22(SOURCE)
N16359410: J1.9(EESDA) J2.12(AUXSDA) R13.2 U2.5(SDA)
N16362829: R14.2 TP2.1 U2.7(WP)
N16374572: D5.2(ANODE) Q3.3 R21.2
N16374891: D6.2(ANODE) Q4.3 R10.2
N16374930: D7.2(ANODE) Q5.3 R11.2
N18222437: R7.1 R8.1 U1.21(FB)
N18284784: JP5.2 JP5.3 U1.11(ADR2)
N18289049: JP4.2 JP4.3 U1.10(ADR1)
N18292359: JP3.2 JP3.3 U1.9(ADR0)
N18306085: JP6.2 U1.4(LOCK)
N18368024: C4.1 E7.1(A) JP2.2 JP2.3 R9.2 U1.1(ON)
N18459479: C3.1 JP1.1 U1.8(CLK_I) Y1.1 Y2.1
N18461854: C2.1 U1.7(CLK_O) Y1.2 Y2.3
N18667288: J1.11(EESCL) J2.11(AUXSCL) R12.2 U2.6(SCL)
N18704667: E12.1(A) Q3.1 R22.2 R152.2 R153.2 U1.15(~{ALERT})
N18712255: C13.1 E19.1(A) R1.2 R2.1 U1.32(UV)
N18712591: E20.1(A) R2.2 R3.1 U1.2(OV)
N18750723: C7.1 E18.1(A) U1.6(TIMER)
N19150519: E13.1(A) R16.2
N19152397: E14.1(A) R15.2
N20179784: R135.2 R136.1 SKT1.25(SENSE-2) SKT1.26(ADC-) SKT1.27(SENSE-1) SKT1.28(SENSE+2) SKT1.29(SENSE+1) SKT1.30(ADC+) SKT1.31(VDD)
N20179796: R137.2 R140.1 SKT1.11(ADR2)
N20179824: R139.2 R142.1 SKT1.9(ADR0)
N20179836: R138.2 R141.1 SKT1.10(ADR1)
N20179848: C5.1 R137.1 R138.1 R139.1 SKT1.5(VCC)
N20179946: D4.2(ANODE) R136.2
N20577435: R151.2 U1.27(SENSE-1)
N20972803: J2.7(GPIO_1) R154.1
N20976156: J2.9(OUTEN_1) R155.1
N21012841: D3.2(ANODE) R17.2 Z1.1(C)
N21043579: D9.2(ANODE) R4.1 Z2.1(C)
N21809093: D8.2(ANODE) R6.2 Z3.1(C)
N22533823: Q15.4(G) R104.2
N22577978: Q9.1(G) R40.1
N22578072: C11.2 R45.1
N22593523: Q11.1(G) R73.1
N22593581: C12.2 R76.1
N22881125: D1.2(ANODE) R5.2
N22886736: D2.2(ANODE) R18.2
N22945727: R80.1 R85.1 R90.1 R92.2 R97.1 R102.1
N22946516: R110.1 R115.1 R117.2 R122.1 R127.1 R132.1
N23045954: R24.1 R25.2 R27.1
N23065324: R29.1 R30.2 R32.1
N23101429: R34.1 R35.2 R37.1
N23113318: R39.1 R41.2 R43.1
N23129335: R44.1 R47.2 R49.1
N23143973: R23.2 R25.1 R26.2
N23155401: R28.2 R30.1 R31.2
N23166852: R33.2 R35.1 R36.2
N23181358: R38.2 R41.1 R42.2
N23204776: R46.2 R47.1 R48.2
N23238552: R56.1 R57.2 R59.1
N23238556: R50.2 R52.1 R53.2
N23238564: R55.2 R57.1 R58.2
N23238578: R65.2 R67.1 R68.2
N23238583: R71.1 R72.2 R75.1
N23238612: R60.2 R62.1 R63.2
N23238895: R51.1 R52.2 R54.1
N23238977: R66.1 R67.2 R69.1
N23239010: R70.2 R72.1 R74.2
N23239014: R61.1 R62.2 R64.1
N23282096: R83.1 R84.2 R86.1
N23282103: R77.2 R79.1 R80.2
N23282108: R78.2 R83.2 R88.2 R95.2 R100.2 R106.1 R108.2 R113.2 R120.2 R125.2 R130.2
N23282114: R82.2 R84.1 R85.2
N23282119: R81.2 R86.2 R91.2 R93.1 R98.2 R103.2
N23282140: R94.2 R96.1 R97.2
N23282145: R100.1 R101.2 R103.1
N23282202: R87.2 R89.1 R90.2
N23282327: R77.1 R82.1 R87.1 R94.1 R99.1 R105.2 R107.1 R112.1 R119.1 R124.1 R129.1
N23282377: R113.1 R114.2 R116.1
N23282381: R107.2 R109.1 R110.2
N23282389: R112.2 R114.1 R115.2
N23282403: R124.2 R126.1 R127.2
N23282405: R130.1 R131.2 R133.1
N23282438: R119.2 R121.1 R122.2
N23282590: R111.2 R116.2 R118.1 R123.2 R128.2 R133.2
N23282708: R108.1 R109.2 R111.1
N23282805: R125.1 R126.2 R128.1
N23282836: R129.2 R131.1 R132.2
N23282840: R120.1 R121.2 R123.1
N23283164: R78.1 R79.2 R81.1
N23283306: R95.1 R96.2 R98.1
N23283339: R99.2 R101.1 R102.2
N23283345: R88.1 R89.2 R91.1
N23714432: Q13.4(G) R134.2
N23715228: Q1.1(G) R143.1
N23715246: Q8.4(G) R144.1
N23716100: Q10.4(G) R146.1
N23716105: Q2.1(G) R145.1
N23716969: Q6.1(G) R147.2
N23716987: Q12.1(G) R148.2
N23717063: Q7.1(G) R149.2
N23717070: Q14.1(G) R150.2
N23747318: J1.14(GPIO) R152.1
N23747809: J2.6(ALERTB) R153.1

Not connected (* = marked no-connect by the designer): J1 1(VUNREG)* 5(MISO)* 6(CS)*; J2 8(OUTEN_0)*; JP1 3*; SKT1 1(ON)* 2(OV)* 6(TIMER)* 7(CLK_O)* 15(~{ALERT})* 16(NC)* 17(GPIO3)* 18(GPIO2)* 19(GPIO1)* 21(FB)* 22(SOURCE)* 23(GATE1)* 24(GATE2)* 32(UV)*; U1 16(NC)*

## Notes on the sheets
sheet 1
- PCB MECHANICAL PARTS
- HIGH CURRENT HOT SWAP CONTROLLER
- WITH I²C COMPATIBLE MONITORING AND EEPROM
sheet 2
- +12V IN
- CONNECTIONS TO PAGES 2 AND 3
- +12V IN
- = HIGH-CURRENT CONNECTIONS
- +12V OUT
- +12V OUT
- 100 AMPS
- GPIO3
- GPIO2
- IN
- ON
- INTVCC
- ON
- (300K)
- OUT
- (SHORT PIN)
- OV
- UV
- FLOAT
- GPIO1
- GND
- GND
- (0.1u)
- GPI01
- SDA
- GPI02
- SCL
- OPT
- CLK
- GPI03
- INT
- ALERT
- EXT
- INT VCC
- EXT 5V
- TIMER
- GND
- GND
- ADR2
- ADR1
- ADR0
- WRITE PROTECT
- GND
- H
- H
- Quik Eval
- TM
- LOCK
- UNLESS OTHERWISE NOTED:
- NC
- NC
- WRITE
- 1. ALL RESISTORS THIS PAGE ARE 1% 0603.
- L
- L
- 2. ALL CAPACITORS THIS PAGE ARE 0603.
- SCL
- GND
- ALERT
- SCL
- SDA
- ASSEMBLY OPTIONS
- LTC SKU#
- SKT 1 ( PAGE 4 )
- DC2024A-A
- NOT STUFFED
- DC2024A-B
- STUFFED
- DC 1613
- HIGH CURRENT HOT SWAP CONTROLLER
- WITH I²C COMPATIBLE MONITORING AND EEPROM
- 9-05-2013
sheet 3
- "RS1"
- PRIMARY SIDE
- (TO BOTTOM SIDE)
- (OPT)
- "Q1"
- PRIMARY SIDE
- SENSE+1
- SENSE-1
- (OPT)
- GATE1
- ADC-
- ADC+
- ADC+
- 1000 uF
- OPTIONAL
- 1000 uF
- OPTIONAL
- SENSE+2
- SENSE-2
- NICHICON P/N UVR1E102MPD
- NICHICON P/N UVR1E102MPD
- OR EQUIVALENT
- OR EQUIVALENT
- (OPT)
- "Q2"
- PRIMARY SIDE
- (OPT)
- (TO BOTTOM SIDE)
- "RS2"
- GATE2
- PRIMARY SIDE
- =HIGH CURRENT CONNECTIONS
- UNLESS OTHERWISE NOTED:
- 1. ALL RESISTORS THIS PAGE ARE 1% 0402.
- OPT
- OPT
- 2. ALL CAPACITORS THIS PAGE ARE 0603.
- 3. ALL 0.003 OHM SENSE RESISTORS ARE SIZE 2512.
- HIGH CURRENT HOT SWAP CONTROLLER
- WITH I²C COMPATIBLE MONITORING AND EEPROM
sheet 4
- "RS1"
- (OPT)
- (FROM TOP SIDE)
- SECONDARY SIDE
- (OPT)
- "Q1"
- SECONDARY SIDE
- (OPT)
- (OPT)
- (OPT)
- "Q2"
- SECONDARY SIDE
- (OPT)
- "RS2"
- SECONDARY SIDE
- (FROM TOP SIDE)
- SECONDARY SIDE STUFFING OPTIONS, THIS PAGE
- =HIGH CURRENT CONNECTIONS
- UNLESS OTHERWISE NOTED:
- 1. ALL RESISTORS THIS PAGE ARE 1% 0402.
- HIGH CURRENT HOT SWAP CONTROLLER
- WITH I²C COMPATIBLE MONITORING AND EEPROM
- 2. ALL OPTIONAL SENSE RESISTORS ARE SIZE 2512.
sheet 5
- OPTIONAL PROGRAMMING SOCKET,
- INSTALLED ON -B ASSEMBLY OPTION
- SOCKET POWER
- SOCKET
- POWER
- 0N
- UNLESS OTHERWISE NOTED:
- 1. ALL RESISTORS THIS PAGE ARE 0603.
- HIGH CURRENT HOT SWAP CONTROLLER
- WITH I²C COMPATIBLE MONITORING AND EEPROM
- WITH I2C COMPATIBLE MONITORING AND EEPROM
- 4-03-2013
